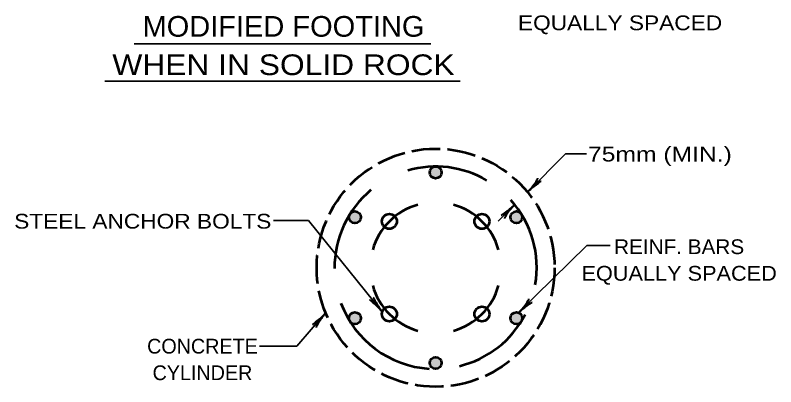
# Model space of a CAD drawing. Extents: x -39 to 816, y -16 to 528.
# Drawn here: x 399.2 to 553.9, y 321.1 to 396.6 of the extents above; entities that cross this region are included whole.
import ezdxf
from ezdxf.enums import TextEntityAlignment as Align

# ---------------------------------------------------------------- set-up
doc = ezdxf.new("R2010")
doc.units = 0
doc.header["$LTSCALE"] = 0.97
doc.linetypes.add('LONG_DASHED', pattern=[7.5, 6, -1.5])
doc.layers.add('1', color=7, linetype='Continuous', lineweight=35)

msp = doc.modelspace()

# ---------------------------------------------------------------- hatches: boundary and pattern name
at = {"layer": '1'}
for points in [[(485.9359, 364.6558, 1), (483.5167, 364.6558, 1)], [(469.523, 355.558, 1), (467.1038, 355.558, 1)], [(502.3488, 355.558, 1), (499.9296, 355.558, 1)], [(469.523, 335.0463, 1), (467.1038, 335.0463, 1)], [(502.3487, 335.0463, 1), (499.9295, 335.0463, 1)], [(485.9359, 325.9486, 1), (483.5167, 325.9486, 1)]]:
    msp.add_hatch(color=256, dxfattribs=at).paths.add_polyline_path(points)

# ---------------------------------------------------------------- linework, layer by layer
for p, q in [((423.3982, 390.8092), (483.7164, 390.8092)), ((417.4207, 383.199), (489.6939, 383.199)), ((497.4714, 354.7614), (500.8074, 358.0974)), ((458.8554, 354.8814), (451.7274, 354.8814)), ((473.8554, 336.3294), (458.8554, 354.8814)), ((462.3354, 336.1134), (456.5034, 329.3934)), ((456.5034, 329.3934), (448.9194, 329.3934))]:
    msp.add_line(p, q, dxfattribs=at)
for points in [[(503.3994, 360.6894), (511.1514, 368.4414), (515.3994, 368.4414)], [(501.5789, 336.1731), (515.4679, 349.7887), (520.2083, 349.7887)]]:
    msp.add_lwpolyline(points, dxfattribs=at)
at = {"layer": '1', "linetype": 'LONG_DASHED', "lineweight": 53}
msp.add_circle((484.7263, 345.3022), 24.192, dxfattribs=at)
at = {"layer": '1', "lineweight": 53}
for centre, radius in [((484.7263, 364.6558), 1.2096), ((468.3134, 355.558), 1.2096), ((475.3178, 354.7107), 1.512), ((494.1348, 354.7107), 1.512), ((501.1392, 355.558), 1.2096), ((475.3178, 335.8937), 1.512), ((494.1348, 335.8937), 1.512), ((468.3134, 335.0463), 1.2096), ((501.1391, 335.0463), 1.2096), ((484.7263, 325.9486), 1.2096)]:
    msp.add_circle(centre, radius, dxfattribs=at)
for radius, start, end in [(20.5632, 59.62188, 105.99903), (20.5632, 129.76139, 180.48594), (20.5632, 350.2187, 41.88924), (13.3056, 105.82662, 164.17338), (13.3056, 15.82662, 74.17338), (13.3056, 195.82662, 254.17338), (13.3056, 285.82662, 344.17338), (20.5632, 200.43579, 266.30804), (20.5632, 283.57599, 332.46404)]:
    msp.add_arc((484.7263, 345.3022), radius, start, end, dxfattribs=at)
at = {"layer": '1', "lineweight": 40}
for centre, major_axis, ratio, start_param, end_param in [((504.0948, 361.8545), (-1.3938, -1.6609), 0.122415, 0.89635335, 3.14159265), ((504.5372, 361.4623), (-1.6526, -1.3521), 0.07063, 3.14071475, 5.41810995), ((499.6784, 357.3275), (-1.6526, -1.3521), 0.07063, 6.28230741, 8.55970261), ((499.6784, 357.3275), (-1.6526, -1.3521), 0.07063, 6.28230741, 8.55970261), ((500.1208, 356.9353), (1.3938, 1.6609), 0.122415, 0.89635335, 3.14159265), ((500.1208, 356.9353), (1.3938, 1.6609), 0.122415, 0.89635335, 3.14159265), ((472.7769, 337.1352), (1.5054, -1.5604), 0.122415, 0.89635335, 3.14159265), ((472.7769, 337.1352), (1.5054, -1.5604), 0.122415, 0.89635335, 3.14159265), ((473.2134, 337.534), (-1.1712, 1.7854), 0.07063, 6.28230741, 8.55970261), ((473.2134, 337.534), (-1.1712, 1.7854), 0.07063, 6.28230741, 8.55970261), ((502.2819, 337.3265), (-1.399, -1.6339), 0.122415, 0.89635335, 3.14159265), ((502.7168, 336.9331), (1.6527, 1.325), 0.07063, 6.28230741, 8.55970261), ((461.2635, 335.2614), (-1.5551, -1.4631), 0.07063, 6.28230741, 8.55970261), ((461.732, 334.9006), (1.2756, 1.7533), 0.122415, 0.89635335, 3.14159265)]:
    msp.add_ellipse(centre, major_axis=major_axis, ratio=ratio, start_param=start_param, end_param=end_param, dxfattribs=at)

# ---------------------------------------------------------------- texts
at = {"layer": '1'}
for s, height, width, p in [('MODIFIED FOOTING', 4.2, 1.05, (453.7874, 392.2456)), ('EQUALLY SPACED', 3, 1.15, (522.2285, 393.5668)), ('WHEN IN SOLID ROCK', 4.2, 1.15, (453.7875, 384.4456)), ('REINF. BARS', 3, 1.05, (534.2453, 348.068)), ('EQUALLY SPACED', 3, 1.1, (534.2453, 342.668))]:
    msp.add_text(s, height=height, dxfattribs=dict(at, width=width)).set_placement(p, align=Align.CENTER)
for s, width, p in [('75mm (MIN.)', 1.25, (515.7115, 366.8813)), ('STEEL ANCHOR BOLTS', 1.15, (399.0136, 353.2494))]:
    msp.add_text(s, height=3, dxfattribs=dict(at, width=width)).set_placement(p)
for s, p in [('CONCRETE', (437.3038, 327.8574)), ('CYLINDER', (437.3039, 322.4574))]:
    msp.add_text(s, height=3, dxfattribs=at).set_placement(p, align=Align.CENTER)

doc.saveas('drawing.dxf')
